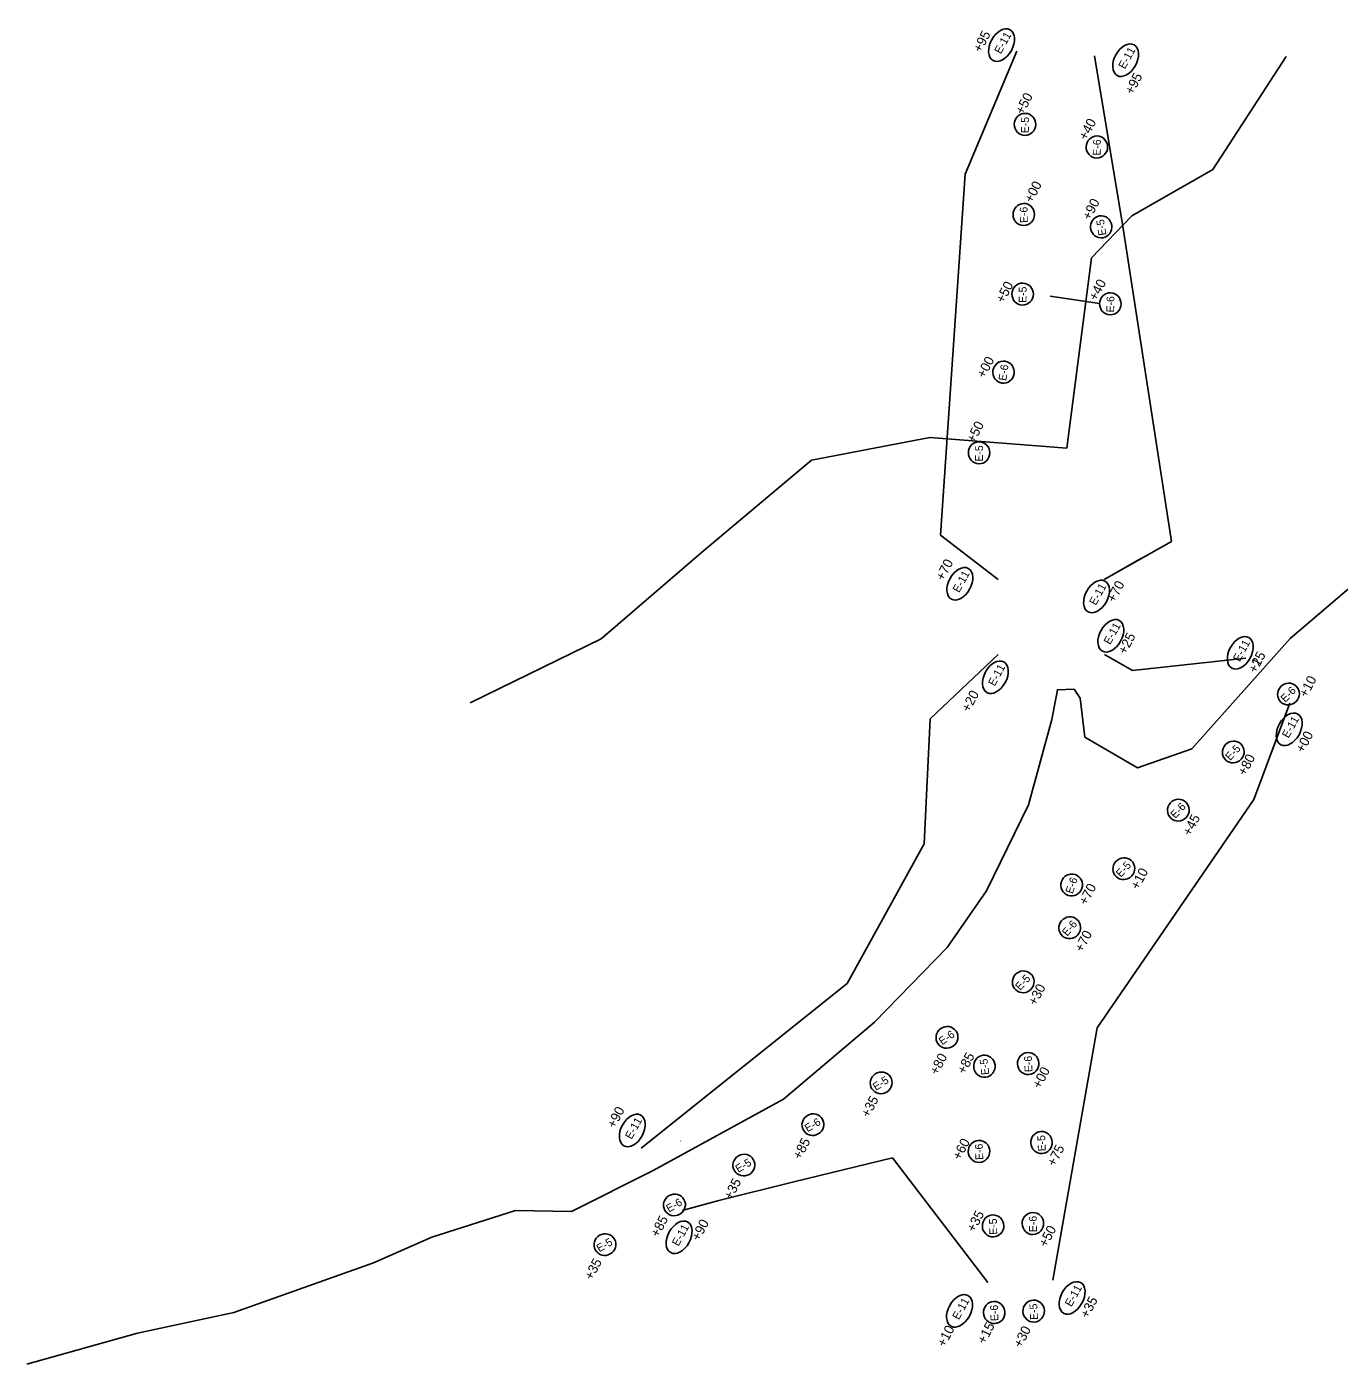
# Model space of a CAD drawing. Extents: x 1405136 to 1406586, y 1842078 to 1843486.
# Drawn here: x 1405136 to 1405956, y 1842078 to 1842913 of the extents above; entities that cross this region are included whole.
import ezdxf

# ---------------------------------------------------------------- set-up
doc = ezdxf.new("R2010")
doc.units = 0
for name, color, linetype in [('53', 7, 'Continuous'), ('8', 7, 'Continuous'), ('Level 44', 7, 'Continuous'), ('X_ARROWS_EXIST', 7, 'Continuous'), ('X_ARROWS_LEGEND', 7, 'Continuous')]:
    doc.layers.add(name, color=color, linetype=linetype)

msp = doc.modelspace()

# ---------------------------------------------------------------- linework, layer by layer
at = {"layer": '53'}
for points in [[(1405786.35, 1842650.25), (1405801.74, 1842769.06), (1405826.86, 1842795.34), (1405877.57, 1842824.23), (1405923.3, 1842894.8)], [(1405786.35, 1842650.25), (1405801.74, 1842769.06), (1405826.86, 1842795.34), (1405877.57, 1842824.23), (1405923.3, 1842894.8)], [(1405786.35, 1842650.25), (1405801.74, 1842769.06), (1405826.86, 1842795.34), (1405877.57, 1842824.23), (1405923.3, 1842894.8)], [(1405413.51, 1842491.12), (1405495.31, 1842531.1), (1405557.75, 1842584.71), (1405626.77, 1842642.77), (1405700.71, 1842656.75), (1405786.35, 1842650.25)], [(1405413.51, 1842491.12), (1405495.31, 1842531.1), (1405557.75, 1842584.71), (1405626.77, 1842642.77), (1405700.71, 1842656.75), (1405786.35, 1842650.25)], [(1405413.51, 1842491.12), (1405495.31, 1842531.1), (1405557.75, 1842584.71), (1405626.77, 1842642.77), (1405700.71, 1842656.75), (1405786.35, 1842650.25)], [(1405979.39, 1842576.86), (1405925.75, 1842531.28), (1405864.36, 1842462.23), (1405830.37, 1842450.36), (1405797.58, 1842469.66), (1405794.52, 1842493.97), (1405790.79, 1842499.66), (1405780.4, 1842499.24), (1405776.85, 1842480.61), (1405762.37, 1842427.25), (1405736.17, 1842373.6), (1405711.52, 1842338.11), (1405666.01, 1842291.47), (1405609.34, 1842243.36), (1405527.76, 1842198.91), (1405476.73, 1842173.24), (1405441.84, 1842173.97), (1405389.48, 1842157.23), (1405353, 1842141.1), (1405265.73, 1842110.16), (1405205.51, 1842097.2), (1405136.42, 1842077.8)], [(1405979.39, 1842576.86), (1405925.75, 1842531.28), (1405864.36, 1842462.23), (1405830.37, 1842450.36), (1405797.58, 1842469.66), (1405794.52, 1842493.97), (1405790.79, 1842499.66), (1405780.4, 1842499.24), (1405776.85, 1842480.61), (1405762.37, 1842427.25), (1405736.17, 1842373.6), (1405711.52, 1842338.11), (1405666.01, 1842291.47), (1405609.34, 1842243.36), (1405527.76, 1842198.91), (1405476.73, 1842173.24), (1405441.84, 1842173.97), (1405389.48, 1842157.23), (1405353, 1842141.1), (1405265.73, 1842110.16), (1405205.51, 1842097.2), (1405136.42, 1842077.8)], [(1405979.39, 1842576.86), (1405925.75, 1842531.28), (1405864.36, 1842462.23), (1405830.37, 1842450.36), (1405797.58, 1842469.66), (1405794.52, 1842493.97), (1405790.79, 1842499.66), (1405780.4, 1842499.24), (1405776.85, 1842480.61), (1405762.37, 1842427.25), (1405736.17, 1842373.6), (1405711.52, 1842338.11), (1405666.01, 1842291.47), (1405609.34, 1842243.36), (1405527.76, 1842198.91), (1405476.73, 1842173.24), (1405441.84, 1842173.97), (1405389.48, 1842157.23), (1405353, 1842141.1), (1405265.73, 1842110.16), (1405205.51, 1842097.2), (1405136.42, 1842077.8)]]:
    msp.add_lwpolyline(points, dxfattribs=at)
at = {"layer": 'Level 44'}
for p, q in [((1405722.73, 1842821.31), (1405755.02, 1842898.15)), ((1405803.54, 1842895.25), (1405821.46, 1842787.38)), ((1405707.36, 1842595.9), (1405722.73, 1842821.31)), ((1405743.38, 1842568.08), (1405707.36, 1842595.9)), ((1405743.46, 1842521.22), (1405700.96, 1842480.99)), ((1405809.72, 1842521.35), (1405827.37, 1842511.21)), ((1405809.72, 1842521.35), (1405827.37, 1842511.21)), ((1405809.72, 1842521.35), (1405827.37, 1842511.21)), ((1405898.07, 1842519), (1405827.37, 1842511.21)), ((1405903.21, 1842430.61), (1405925.56, 1842490.89)), ((1405700.96, 1842480.99), (1405697.06, 1842403.05)), ((1405649.02, 1842315.71), (1405697.06, 1842403.05)), ((1405649.02, 1842315.71), (1405520.34, 1842212.74)), ((1405777.45, 1842130.43), (1405805.29, 1842287.98)), ((1405677.35, 1842206.75), (1405736.92, 1842128.78)), ((1405568.85, 1842180.06), (1405545.93, 1842173.79))]:
    msp.add_line(p, q, dxfattribs=at)
for points in [[(1405805.29, 1842287.98), (1405903.21, 1842430.61)], [(1405568.85, 1842180.06), (1405615.77, 1842191.78), (1405677.35, 1842206.75)]]:
    msp.add_lwpolyline(points, dxfattribs=at)
at = {"layer": 'X_ARROWS_EXIST'}
msp.add_line((1405806.74, 1842740.51), (1405775.84, 1842745.08), dxfattribs=at)
at = {"layer": 'X_ARROWS_LEGEND'}
for p, q in [((1405821.46, 1842787.38), (1405851.57, 1842591.95)), ((1405851.57, 1842591.95), (1405809.64, 1842568.16)), ((1405832.88, 1842581.52), (1405809.64, 1842568.16))]:
    msp.add_line(p, q, dxfattribs=at)
msp.add_arc((1405656.21, 1841885.3), 350, 108.49892, 108.49897, dxfattribs=at)
msp.add_arc((1405656.21, 1841885.3), 350, 108.49892, 108.49897, dxfattribs=at)
msp.add_arc((1405656.21, 1841885.3), 350, 108.49892, 108.49897, dxfattribs=at)
for centre, major_axis, ratio in [((1405745.48, 1842902.03), (5.28, 9.6), 0.638788), ((1405823, 1842892.59), (5.28, 9.6), 0.638788), ((1405823, 1842892.59), (5.28, 9.6), 0.638788), ((1405760.14, 1842852.47), (-0.1, -6.88), 0.97521), ((1405805.03, 1842838.36), (-0.14, -6.88), 0.97521), ((1405805.03, 1842838.36), (-0.14, -6.88), 0.97521), ((1405759.36, 1842796.22), (0.14, -6.88), 0.97521), ((1405807.73, 1842788.45), (1.08, -6.8), 0.97521), ((1405807.73, 1842788.45), (1.08, -6.8), 0.97521), ((1405758.66, 1842746.45), (-0.1, -6.88), 0.97521), ((1405813.45, 1842740.37), (-0.14, -6.88), 0.97521), ((1405813.45, 1842740.37), (-0.14, -6.88), 0.97521), ((1405746.74, 1842697.69), (-1.02, -6.8), 0.97521), ((1405731.44, 1842647.27), (-0.09, -6.88), 0.97521), ((1405719.42, 1842565.45), (5.28, 9.6), 0.638788), ((1405804.83, 1842557.53), (5.28, 9.6), 0.638788), ((1405813.76, 1842532.95), (5.28, 9.6), 0.638788), ((1405894.63, 1842522.3), (5.28, 9.6), 0.638788), ((1405894.63, 1842522.3), (5.28, 9.6), 0.638788), ((1405741.61, 1842507.04), (5.28, 9.6), 0.638788), ((1405741.61, 1842507.04), (5.28, 9.6), 0.638788), ((1405924.76, 1842496.55), (-4.76, -4.97), 0.97521), ((1405925.21, 1842474.52), (5.28, 9.6), 0.638788), ((1405925.21, 1842474.52), (5.28, 9.6), 0.638788), ((1405925.21, 1842474.52), (5.28, 9.6), 0.638788), ((1405890.27, 1842460.37), (-4.69, -5.04), 0.97521), ((1405855.92, 1842424.02), (-4.72, -5.01), 0.97521), ((1405821.89, 1842387.4), (-4.63, -5.09), 0.97521), ((1405789.29, 1842377.26), (-2.19, -6.52), 0.97521), ((1405788.1, 1842350.54), (-4.46, -5.24), 0.97521), ((1405759.02, 1842316.73), (-4.63, -5.09), 0.97521), ((1405711.36, 1842282.06), (-5.66, -3.92), 0.97521), ((1405734.76, 1842264.01), (0.84, -6.83), 0.97521), ((1405762.13, 1842265.68), (0.32, -6.87), 0.97521), ((1405670.27, 1842253.58), (-5.75, -3.77), 0.97521), ((1405670.27, 1842253.58), (-5.75, -3.77), 0.97521), ((1405514.76, 1842223.89), (5.28, 9.6), 0.638788), ((1405627.61, 1842227.51), (-5.94, -3.47), 0.97521), ((1405627.61, 1842227.51), (-5.94, -3.47), 0.97521), ((1405731.42, 1842210.8), (0.28, -6.88), 0.97521), ((1405770.44, 1842216.33), (0.32, -6.87), 0.97521), ((1405584.47, 1842202.23), (-5.92, -3.51), 0.97521), ((1405584.47, 1842202.23), (-5.92, -3.51), 0.97521), ((1405541.11, 1842177.35), (-5.96, -3.43), 0.97521), ((1405541.11, 1842177.35), (-5.96, -3.43), 0.97521), ((1405544.03, 1842157.12), (5.28, 9.6), 0.638788), ((1405544.03, 1842157.12), (5.28, 9.6), 0.638788), ((1405740.2, 1842164.23), (0.17, -6.88), 0.97521), ((1405765.05, 1842165.72), (0.12, -6.88), 0.97521), ((1405497.69, 1842152.54), (-5.97, -3.42), 0.97521), ((1405789.55, 1842119.24), (5.28, 9.6), 0.638788), ((1405719.22, 1842111.15), (5.28, 9.6), 0.638788), ((1405719.22, 1842111.15), (5.28, 9.6), 0.638788), ((1405740.89, 1842110.11), (0.28, -6.88), 0.97521), ((1405765.55, 1842111.01), (0.32, -6.87), 0.97521)]:
    msp.add_ellipse(centre, major_axis=major_axis, ratio=ratio, dxfattribs=at)

# ---------------------------------------------------------------- texts
at = {"layer": '8'}
for s, p in [('+95', (1405732.57, 1842896.9)), ('+95', (1405827.46, 1842870.62)), ('+95', (1405827.46, 1842870.62)), ('+50', (1405758.95, 1842858.16)), ('+40', (1405798.6, 1842842.09)), ('+40', (1405798.6, 1842842.09)), ('+00', (1405764.57, 1842803)), ('+90', (1405800.76, 1842792.1)), ('+90', (1405800.76, 1842792.1)), ('+50', (1405746.79, 1842740.3)), ('+40', (1405804.79, 1842741.7)), ('+40', (1405804.79, 1842741.7)), ('+00', (1405734.91, 1842693.39)), ('+50', (1405728.44, 1842652.93)), ('+70', (1405709.23, 1842566.81)), ('+70', (1405816.22, 1842553.27)), ('+25', (1405823.13, 1842520.79)), ('+15', (1405904.46, 1842509.09)), ('+25', (1405904.46, 1842509.09)), ('+10', (1405936.21, 1842493.91)), ('+20', (1405725.33, 1842484.75)), ('+20', (1405725.33, 1842484.75)), ('+00', (1405934.16, 1842459.33)), ('+00', (1405934.16, 1842459.33)), ('+00', (1405934.16, 1842459.33)), ('+80', (1405897.89, 1842444.95)), ('+45', (1405863.49, 1842407.35)), ('+10', (1405831.04, 1842373.81)), ('+70', (1405798.62, 1842364.1)), ('+70', (1405796.04, 1842334.8)), ('+30', (1405766.96, 1842301.35)), ('+80', (1405705.48, 1842257.99)), ('+85', (1405722.61, 1842258.52)), ('+00', (1405769.64, 1842249.5)), ('+35', (1405662.63, 1842231.4)), ('+90', (1405503.9, 1842224.68)), ('+85', (1405619.95, 1842205.16)), ('+85', (1405619.95, 1842205.16)), ('+60', (1405719.67, 1842204.85)), ('+75', (1405778.77, 1842200.91)), ('+35', (1405576.82, 1842179.96)), ('+35', (1405576.82, 1842179.96)), ('+85', (1405531.11, 1842156.6)), ('+85', (1405531.11, 1842156.6)), ('+90', (1405556.58, 1842154.3)), ('+90', (1405556.58, 1842154.3)), ('+35', (1405728.59, 1842159.79)), ('+50', (1405773.63, 1842150.41)), ('+35', (1405489.71, 1842129.86)), ('+35', (1405799.5, 1842106.04)), ('+10', (1405710.02, 1842088.02)), ('+15', (1405735.15, 1842089.9)), ('+30', (1405757.81, 1842087.63))]:
    msp.add_text(s, height=6, rotation=62.48407, dxfattribs=at).set_placement(p)
at = {"layer": 'X_ARROWS_LEGEND'}
for s, height, rotation, p in [('E-11', 4.999, 61.16855, (1405745.02, 1842896.1)), ('E-11', 4.999, 61.16855, (1405822.54, 1842886.66)), ('E-11', 4.999, 61.16855, (1405822.54, 1842886.66)), ('E-5', 4.876, 89.18548, (1405762.5, 1842846.94)), ('E-6', 4.876, 88.80351, (1405807.36, 1842832.95)), ('E-6', 4.876, 88.80351, (1405807.36, 1842832.95)), ('E-6', 4.876, 91.17691, (1405761.91, 1842790.92)), ('E-5', 4.876, 98.99885, (1405811, 1842783.41)), ('E-5', 4.876, 98.99885, (1405811, 1842783.41)), ('E-5', 4.876, 89.18548, (1405761.02, 1842740.93)), ('E-6', 4.876, 88.80351, (1405815.78, 1842734.97)), ('E-6', 4.876, 88.80351, (1405815.78, 1842734.97)), ('E-6', 4.876, 81.47371, (1405748.36, 1842692.03)), ('E-5', 4.876, 89.25852, (1405733.81, 1842641.75)), ('E-11', 4.999, 61.16855, (1405718.96, 1842559.52)), ('E-11', 4.999, 61.16855, (1405804.37, 1842551.6)), ('E-11', 4.999, 61.16855, (1405813.31, 1842527.02)), ('E-11', 4.999, 61.16855, (1405894.17, 1842516.37)), ('E-11', 4.999, 61.16855, (1405894.17, 1842516.37)), ('E-11', 4.999, 61.16855, (1405741.16, 1842501.11)), ('E-11', 4.999, 61.16855, (1405741.16, 1842501.11)), ('E-6', 4.876, 46.24707, (1405922.82, 1842491)), ('E-11', 4.999, 61.16855, (1405924.75, 1842468.59)), ('E-11', 4.999, 61.16855, (1405924.75, 1842468.59)), ('E-11', 4.999, 61.16855, (1405924.75, 1842468.59)), ('E-5', 4.876, 47.07838, (1405888.31, 1842454.69)), ('E-6', 4.876, 46.69248, (1405854.03, 1842418.45)), ('E-5', 4.876, 47.6727, (1405820, 1842381.7)), ('E-6', 4.876, 71.41875, (1405789.89, 1842371.41)), ('E-6', 4.876, 49.58193, (1405786.49, 1842344.88)), ('E-5', 4.876, 47.6727, (1405757.12, 1842311.03)), ('E-6', 4.876, 34.70066, (1405708.35, 1842277.01)), ('E-5', 4.876, 97.02869, (1405737.85, 1842258.86)), ('E-6', 4.876, 92.66768, (1405764.82, 1842260.44)), ('E-5', 4.876, 33.27156, (1405667.02, 1842248.53)), ('E-5', 4.876, 33.27156, (1405667.02, 1842248.53)), ('E-11', 4.999, 61.16855, (1405514.3, 1842217.96)), ('E-6', 4.876, 30.30358, (1405624.22, 1842222.7)), ('E-6', 4.876, 30.30358, (1405624.22, 1842222.7)), ('E-5', 4.876, 92.71077, (1405773.13, 1842210.96)), ('E-6', 4.876, 92.34911, (1405734.08, 1842205.55)), ('E-5', 4.876, 30.64341, (1405580.99, 1842197.33)), ('E-5', 4.876, 30.64341, (1405580.99, 1842197.33)), ('E-6', 4.876, 29.94796, (1405537.68, 1842172.56)), ('E-6', 4.876, 29.94796, (1405537.68, 1842172.56)), ('E-5', 4.876, 91.41652, (1405742.78, 1842158.8)), ('E-6', 4.876, 91.00292, (1405767.58, 1842160.41)), ('E-11', 4.999, 61.16855, (1405543.58, 1842151.19)), ('E-11', 4.999, 61.16855, (1405543.58, 1842151.19)), ('E-5', 4.876, 29.77368, (1405494.14, 1842147.7)), ('E-11', 4.999, 61.16855, (1405789.09, 1842113.31)), ('E-11', 4.999, 61.16855, (1405718.77, 1842105.22)), ('E-11', 4.999, 61.16855, (1405718.77, 1842105.22)), ('E-6', 4.876, 92.34911, (1405743.55, 1842104.86)), ('E-5', 4.876, 92.71077, (1405768.24, 1842105.64))]:
    msp.add_text(s, height=height, rotation=rotation, dxfattribs=at).set_placement(p)

doc.saveas('drawing.dxf')
